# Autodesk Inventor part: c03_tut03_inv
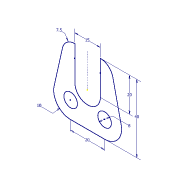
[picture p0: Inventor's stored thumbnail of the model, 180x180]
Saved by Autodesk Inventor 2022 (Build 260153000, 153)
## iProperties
Created: 2017-04
Part Number: c03_tut03_inv
Material: Generic
Document SubType Name: Modeling
Designer: CADCIM 00
Density: 1 g/cm^3
Appearance: Default
Author: CADCIM 00
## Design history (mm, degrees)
sketch "Sketch1"
  geometry: L1 (-10, -20)-(10, -20); L2 (19.756, -7.805)-(14.817, 14.146); L3 (7.5, 20)-(7.5, 0); L4 (-7.5, 0)-(-7.5, 20); L5 (-14.817, 14.146)-(-19.756, -7.805); L6 (0, 0)-(0, 20); C1 r 4 at (-10, -10); C2 r 4 at (10, -10); A1 r 10 centre (10, -10) between (10, -20) and (19.756, -7.805); A2 r 7.5 centre (7.5, 12.5) between (14.817, 14.146) and (7.5, 20); A3 r 7.5 centre (0, 0) between (-7.5, 0) and (7.5, 0); A4 r 7.5 centre (-7.5, 12.5) between (-7.5, 20) and (-14.817, 14.146); A5 r 10 centre (-10, -10) between (-19.756, -7.805) and (-10, -20); 1 further point
  constraints: 12 end point, 10 point on circle, 8 tangent, 7 centre point, 3 coincident, 3 equal radius, 2 equal length, 2 point on line, 1 horizontal, 1 horizontal alignment, 1 parallel, 1 perpendicular, 1 vertical, 3 other
  dimensions: "d0" = 20 distance of L1.start L1.end; "d1" = 7.5 radius of A2; "d2" = 10 radius of A1; "d3" = 15 distance between parallel lines of L4 L3; "d5" = 40 distance from line of L1 L4.end; "d6" = 20 distance of L4.start L4.end; "d7" = 8 diameter of C1
